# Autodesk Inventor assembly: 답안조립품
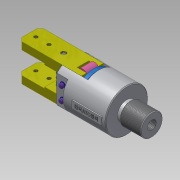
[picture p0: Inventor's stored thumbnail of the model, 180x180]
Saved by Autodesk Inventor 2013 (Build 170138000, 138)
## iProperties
Created: 2019-02
Part Number: 답안조립품
Document SubType Name: Assembly
Designer: Administrator
Author: Administrator
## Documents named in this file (11)
- C:\Users\Administrator\Desktop\490207V1012\답안조립품.iam
- C:\Users\Administrator\Desktop\490207V1012\본체.ipt
- C:\Users\Administrator\Desktop\490207V1012\E-링.ipt
- C:\Users\Administrator\Desktop\490207V1012\O-링.ipt
- C:\Users\Administrator\Desktop\490207V1012\가이드핀.ipt
- C:\Users\Administrator\Desktop\490207V1012\부시.ipt
- C:\Users\Administrator\Desktop\490207V1012\스프링.ipt
- C:\Users\Administrator\Desktop\490207V1012\평행핀 6x28.ipt
- C:\Users\Administrator\Desktop\490207V1012\피스톤.ipt
- C:\Users\Administrator\Desktop\490207V1012\핀.ipt
- C:\Users\Administrator\Desktop\490207V1012\핑거.ipt
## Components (13 placed, 6 different names)
1. E-링:1
2. O-링:1
3. 가이드핀:1
4. 피스톤:1
5. 핀:1
6. 핑거:1
7. O-링:2
8. 핑거:2 — 플러쉬:1
9. 핀:2
10. E-링:2
11. E-링:3
12. E-링:4
13. 가이드핀:2
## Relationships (1: Flush 1)
- 플러쉬:1 [Flush]: 핑거:2
